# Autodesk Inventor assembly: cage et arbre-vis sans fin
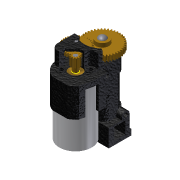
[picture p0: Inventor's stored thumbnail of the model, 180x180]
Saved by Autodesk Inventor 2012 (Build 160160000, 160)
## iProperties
Created: 2011-10
Part Number: cage et arbre-vis sans fin
Document SubType Name: Assembly
Designer: didierf
Author: didierf
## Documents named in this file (8)
- D:\Formulaire\Sujet CIM 4 Poissy\Modélisation_7970_shimano\cage et arbre-vis sans fin.iam
- D:\Formulaire\Sujet CIM 4 Poissy\Modélisation_7970_shimano\cage_moto_reducteur.ipt
- D:\Formulaire\Sujet CIM 4 Poissy\Modélisation_7970_shimano\Mobile vis sans fin.iam
- D:\Formulaire\Sujet CIM 4 Poissy\Modélisation_7970_shimano\Butée axiale vis sans fin.ipt
- D:\Formulaire\Sujet CIM 4 Poissy\Modélisation_7970_shimano\axe engr_cyl inter.ipt
- D:\Formulaire\Sujet CIM 4 Poissy\Modélisation_7970_shimano\Mobile intermédiaire 37 dents m0,25 - 10 dents m0,3.iam
- D:\Formulaire\Sujet CIM 4 Poissy\Modélisation_7970_shimano\moteur DC.ipt
- D:\Formulaire\Sujet CIM 4 Poissy\Modélisation_7970_shimano\arbre moteur et pignon 11 dents m0,25.iam
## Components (7 placed, 7 different names)
1. cage_moto_reducteur:1 — position axiale vis / cage, coaxialité axe inter / cage, Affleurement axe inter / cage, butée axiale mobile inter / cage, Affleurement:3, Angle:2, pos1 butée axiale, pos2 butée axiale, pos3 butée axiale
2. Mobile vis sans fin:1 [sub-assembly] — position axiale vis / cage, Rotation:1, Placage:8
3. Butée axiale vis sans fin:1 — pos1 butée axiale, pos2 butée axiale, pos3 butée axiale
4. axe engr_cyl inter:1 — coaxialité axe inter / cage, Affleurement axe inter / cage, coaxialité axe inter / mobile inter
5. Mobile intermédiaire 37 dents m0,25 - 10 dents m0,3:1 [sub-assembly] — coaxialité axe inter / mobile inter, butée axiale mobile inter / cage, Rotation:1, Rotation:2
6. moteur DC:1 — Affleurement:3, coaxialité arbre moteur, position axiale arbre moteur
7. arbre moteur et pignon 11 dents m0,25:1 [sub-assembly] — coaxialité arbre moteur, position axiale arbre moteur, Rotation:2
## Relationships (15: Mate 10, Flush 2, RelateRotation 2, Angle 1)
- position axiale vis / cage [Mate]: cage_moto_reducteur:1 ↔ Mobile vis sans fin:1
- coaxialité axe inter / cage [Mate]: cage_moto_reducteur:1 ↔ axe engr_cyl inter:1
- Affleurement axe inter / cage [Flush]: cage_moto_reducteur:1 ↔ axe engr_cyl inter:1
- coaxialité axe inter / mobile inter [Mate]: axe engr_cyl inter:1 ↔ Mobile intermédiaire 37 dents m0,25 - 10 dents m0,3:1
- butée axiale mobile inter / cage [Mate]: cage_moto_reducteur:1 ↔ Mobile intermédiaire 37 dents m0,25 - 10 dents m0,3:1
- Rotation:1 [RelateRotation]: Mobile vis sans fin:1 ↔ Mobile intermédiaire 37 dents m0,25 - 10 dents m0,3:1
- Affleurement:3 [Flush]: cage_moto_reducteur:1 ↔ moteur DC:1
- coaxialité arbre moteur [Mate]: moteur DC:1 ↔ arbre moteur et pignon 11 dents m0,25:1
- position axiale arbre moteur [Mate]: moteur DC:1 ↔ arbre moteur et pignon 11 dents m0,25:1
- Rotation:2 [RelateRotation]: Mobile intermédiaire 37 dents m0,25 - 10 dents m0,3:1 ↔ arbre moteur et pignon 11 dents m0,25:1
- Placage:8 [Mate]: Mobile vis sans fin:1
- Angle:2: cage_moto_reducteur:1
- pos1 butée axiale [Mate]: cage_moto_reducteur:1 ↔ Butée axiale vis sans fin:1
- pos2 butée axiale [Mate]: cage_moto_reducteur:1 ↔ Butée axiale vis sans fin:1
- pos3 butée axiale [Mate]: cage_moto_reducteur:1 ↔ Butée axiale vis sans fin:1
